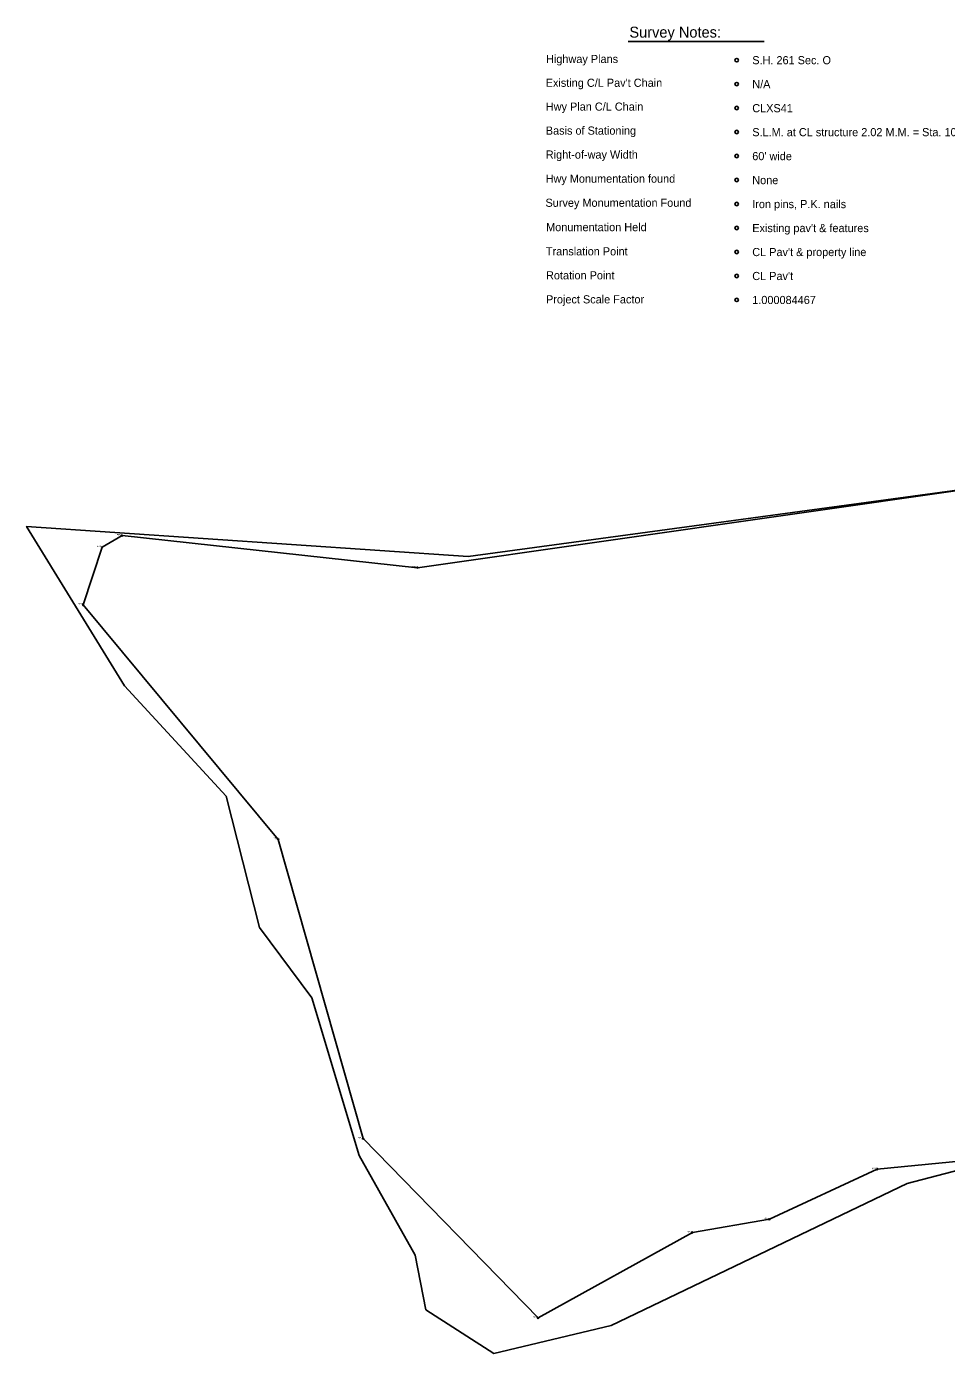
# Model space of a CAD drawing. Extents: x 1713517 to 1720188, y 392280 to 397587.
# Drawn here: x 1713517 to 1715098, y 394364 to 396645 of the extents above; entities that cross this region are included whole.
import ezdxf

# ---------------------------------------------------------------- set-up
doc = ezdxf.new("R2010")
doc.units = 0
for name, color, linetype in [('Default', 7, 'Continuous'), ('DV_X_Property_Line', 7, 'Continuous'), ('GK_Visualization', 7, 'Continuous'), ('SC_Scratch1', 7, 'Continuous'), ('SH_Data', 7, 'Continuous')]:
    doc.layers.add(name, color=color, linetype=linetype)

msp = doc.modelspace()

# ---------------------------------------------------------------- linework, layer by layer
at = {"layer": 'Default'}
msp.add_line((1714551.4, 396619.1), (1714784.9, 396619.1), dxfattribs=at)
for centre in [(1714737.7, 396587), (1714737.7, 396545.8), (1714737.7, 396504.6), (1714737.7, 396463.4), (1714737.7, 396422.2), (1714737.7, 396381), (1714737.7, 396339.7), (1714737.7, 396298.5), (1714737.7, 396257.3), (1714737.7, 396216.1), (1714737.7, 396174.9)]:
    msp.add_circle(centre, 3, dxfattribs=at)
at = {"layer": 'DV_X_Property_Line'}
for p, q in [((1714189.2, 395714.6), (1715724.6, 395933.8)), ((1713647.2, 395750), (1713681.3, 395769.8)), ((1713681.3, 395769.8), (1714189.2, 395714.6)), ((1713614.4, 395651), (1713647.2, 395750)), ((1713949.6, 395247.8), (1713614.4, 395651)), ((1714095.7, 394733.7), (1713949.6, 395247.8)), ((1714396.3, 394425.3), (1714095.7, 394733.7)), ((1715329, 394715.7), (1714979.2, 394681)), ((1714979.2, 394681), (1714793.8, 394595.1)), ((1714793.8, 394595.1), (1714661.5, 394572.2)), ((1714661.5, 394572.2), (1714396.3, 394425.3))]:
    msp.add_line(p, q, dxfattribs=at)
at = {"layer": 'GK_Visualization'}
for p, q in [((1713679.9, 395768.4), (1713682.6, 395771.1)), ((1713679.9, 395771.1), (1713682.6, 395768.4)), ((1713645.8, 395748.6), (1713648.5, 395751.3)), ((1713645.8, 395751.3), (1713648.5, 395748.6)), ((1714187.9, 395713.3), (1714190.5, 395716)), ((1714187.9, 395716), (1714190.5, 395713.3)), ((1713613.1, 395649.6), (1713615.8, 395652.3)), ((1713613.1, 395652.3), (1713615.8, 395649.6)), ((1713948.3, 395246.5), (1713951, 395249.1)), ((1713948.3, 395249.1), (1713951, 395246.5)), ((1714094.4, 394732.3), (1714097, 394735)), ((1714094.4, 394735), (1714097, 394732.3)), ((1714977.9, 394679.7), (1714980.5, 394682.4)), ((1714977.9, 394682.4), (1714980.5, 394679.7)), ((1714792.5, 394593.7), (1714795.2, 394596.4)), ((1714792.5, 394596.4), (1714795.2, 394593.7)), ((1714660.2, 394570.8), (1714662.9, 394573.5)), ((1714660.2, 394573.5), (1714662.9, 394570.8)), ((1714394.9, 394424), (1714397.6, 394426.7)), ((1714394.9, 394426.7), (1714397.6, 394424))]:
    msp.add_line(p, q, dxfattribs=at)
at = {"layer": 'SC_Scratch1'}
for points in [[(1714275.9, 395733.7), (1715724.4, 395930.4), (1715740.2, 395817.2), (1715783.5, 395632.6), (1715848.9, 395468.7), (1716073.9, 395030.2)], [(1716073.9, 395030.2), (1715318.2, 394731.5), (1715030.5, 394656.5), (1714522.1, 394412.5), (1714320.5, 394364.3), (1714203.2, 394439.6), (1714185.1, 394533), (1714088.8, 394704.6), (1714007.6, 394975.7), (1713917.4, 395096.1), (1713860.2, 395322), (1713685.7, 395511.7), (1713517.2, 395785.7), (1714275.9, 395733.7)]]:
    msp.add_lwpolyline(points, dxfattribs=at)

# ---------------------------------------------------------------- texts
at = {"layer": 'Default'}
for s, height, p in [('Survey Notes:', 18.75, (1714553.2, 396625.7)), ('Highway Plans', 14, (1714410, 396582)), ("Existing C/L Pav't Chain", 14, (1714409.4, 396541.1)), ('Hwy Plan C/L Chain', 14, (1714409.6, 396500.1)), ('Basis of Stationing', 14, (1714409.6, 396458.9)), ('Right-of-way Width', 14, (1714409.6, 396417.7)), ('Hwy Monumentation found', 14, (1714409.3, 396376.3)), ('Survey Monumentation Found', 14, (1714409.1, 396334.9)), ('Monumentation Held', 14, (1714410.2, 396293)), ('Translation Point', 14, (1714409.8, 396251.4)), ('Rotation Point', 14, (1714410, 396210.2)), ('Project Scale Factor', 14, (1714410, 396168.9))]:
    msp.add_text(s, height=height, dxfattribs=at).set_placement(p)
at = {"layer": 'GK_Visualization'}
for s, p in [('PP64', (1713672.1, 395769.8)), ('PP63', (1713638, 395750)), ('PP65', (1714180, 395714.6)), ('PP62', (1713605.2, 395651)), ('PP61', (1713941.5, 395247.8)), ('PP60', (1714086.3, 394733.7)), ('PP56', (1714969.9, 394681)), ('PP57', (1714784.7, 394595.1)), ('PP58', (1714652.4, 394572.2)), ('PP59', (1714387.1, 394425.3))]:
    msp.add_text(s, height=2.8, dxfattribs=at).set_placement(p)
at = {"layer": 'SH_Data'}
for s, p in [('S.H. 261 Sec. O', (1714764.4, 396579.9)), ('N/A', (1714764.4, 396538.7)), ('CLXS41', (1714764.4, 396497.4)), ('S.L.M. at CL structure 2.02 M.M. = Sta. 106+65.6', (1714764.4, 396456.2)), ("60' wide", (1714764.4, 396415)), ('None', (1714764.4, 396373.8)), ('Iron pins, P.K. nails', (1714764.4, 396332.6)), ("Existing pav't & features", (1714764.4, 396291.4)), ("CL Pav't & property line", (1714764.4, 396250.2)), ("CL Pav't", (1714764.4, 396209)), ('1.000084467', (1714764.4, 396167.8))]:
    msp.add_text(s, height=14, rotation=360, dxfattribs=at).set_placement(p)

doc.saveas('drawing.dxf')
